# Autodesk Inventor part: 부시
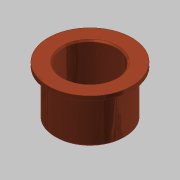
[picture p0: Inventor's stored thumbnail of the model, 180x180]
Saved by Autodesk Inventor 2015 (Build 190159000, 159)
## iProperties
Created: 2015-10
Part Number: 부시
Document SubType Name: Modeling
Designer: mdu
Density: 7.86 g/cm^3
Material: 강철, 연강
Mass: 246.97 g
Surface Area: 129.264 cm^2
Volume: 31.4212 cm^3
Appearance: 구리 - 새틴
Author: mdu
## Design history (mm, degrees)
sketch "스케치1"
  geometry: C1 r 31 at (0, 0) reference; C2 r 25 at (0, 0) reference; C3 r 30 at (0, 0) reference; 1 further point
  node "참조1"
  node "참조2"
  node "참조4"
extrude "돌출1" new body sketch "스케치1" distance "d0" = 3; taper "d1" = 0 deg
extrude "돌출2" join sketch "스케치1" distance "d2" = 35; taper "d3" = 0 deg
chamfer "모따기1" distance "d6" = 1; stored, may be unused: second distance "d7" = 2, angle "d8" = 45 deg
sketch "스케치3"
  geometry: C1 r 19 at (0, 0); 1 further point
  constraints: 1 centre point, 1 coincident
  dimensions: "d13" = 38 diameter of C1
extrude "돌출4" cut sketch "스케치3" stored distance "d14" = 10; taper "d15" = 0 deg
chamfer "모따기3" distance "d16" = 1; stored, may be unused: second distance "d17" = 2, angle "d18" = 45 deg
node "솔리드1"
